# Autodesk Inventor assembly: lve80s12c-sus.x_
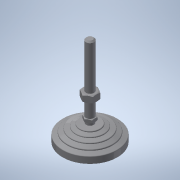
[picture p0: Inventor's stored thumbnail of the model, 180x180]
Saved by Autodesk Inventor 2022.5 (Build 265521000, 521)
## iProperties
Part Number: lve80s12c-sus.x_
Material: 一般
Document SubType Name: Assembly
Designer: ImaoCorp
Sending System: SOLIDWORKS 2017-2017317
MC: AMD64
MC_MODEL: Intel64 Family 6 Model 60 Stepping 3, GenuineIntel
OS: Windows_NT
FRU: Parasolid Version 29.0, build 201,  4-17-2017
FORMAT: text
GUISE: transmit
KEY: lve80s12c-sus
FILE: lve80s12c-sus.x_t
DATE: Mon Jul 01 18:22:10 2019
Author: ImaoCorp
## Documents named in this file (3)
- X:\14_SW2022-Inv2022\00_全2023-1023新製品(TCC)まで\l\lve80s12c-sus\LVE80S12C-SUS.iam
- X:\14_SW2022-Inv2022\00_全2023-1023新製品(TCC)まで\l\lve80s12c-sus\lve80s12c-sus_01.ipt
- X:\14_SW2022-Inv2022\00_全2023-1023新製品(TCC)まで\l\lve80s12c-sus\lve80s12c-sus_02.ipt
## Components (2 placed, 2 different names)
1. lve80s12c-sus_01
2. lve80s12c-sus_02
